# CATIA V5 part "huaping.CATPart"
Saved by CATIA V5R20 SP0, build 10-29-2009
Part number: 花瓶
Material "DS star": density 1000 kg/m3
Material "Bathroom Floor": density 2770 kg/m3, Young's modulus 6e+10 Pa, Poisson ratio 0.3
Bounding box of the stored display mesh (mm): x -48.272 to 51.35, y -48.272 to 48.223, z -0.434 to 150.36
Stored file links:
  F:\huaping.CATPart
  D:\CATIA\win_b64\startup\materials\Catalog.CATMaterial
  D:\CATIA\win_b64\startup\materials\DS_star.jpg
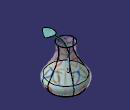
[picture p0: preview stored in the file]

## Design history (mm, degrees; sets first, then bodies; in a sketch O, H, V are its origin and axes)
Body1 (main body), material "DS star"
  Set1
    Plane1: type Offset, RefPlane xy-plane, Offset 20
    Plane2: type Offset, RefPlane Plane1, Offset 20
    Plane3: type Offset, RefPlane Plane2, Offset 20
    Plane4: type Offset, RefPlane Plane3, Offset 20
    Plane5: type Offset, RefPlane Plane4, Offset 20
    Sketch1 on xy-plane, origin (0, 0, 0), H (1, 0, 0), V (0, 1, 0)
      circle A1 centre (0, 0) radius 38.3817
    Sketch2 on Plane2, origin (0, 0, 40), H (1, 0, 0), V (0, 1, 0)
      circle A1 centre (0, 0) radius 37.6815
    Sketch3 on Plane3, origin (0, 0, 60), H (1, 0, 0), V (0, 1, 0)
      circle A1 centre (0, 0) radius 25.6953
    Sketch4 on Plane4, origin (0, 0, 80), H (1, 0, 0), V (0, 1, 0)
      circle A1 centre (0, 0) radius 19.4702
    Sketch5 on Plane5, origin (0, 0, 100), H (1, 0, 0), V (0, 1, 0)
      circle A1 centre (0, 0) radius 20.5162
    Sketch6 on Plane1, origin (0, 0, 20), H (1, 0, 0), V (0, 1, 0)
      circle A1 centre (0, 0) radius 48.3055
  Loft1: solid, Sections (Sketch5; Sketch4; Sketch3; Sketch2; Sketch6; Sketch1)
  Shell1: IntOffset 1, ExtOffset 0
  Shell2: IntOffset 1, Face face of Loft1, ExtOffset 0
Body2, material "Bathroom Floor"
  Sketch7 on zx-plane, origin (0, 0, 0), H (-1, 0, 0), V (0, 0, 1)
    axis line L1 (0, 114.6746) -> (0, -23.121)
    point P3 (0, 27.1114)
    line L2 (0, 27.1114) -> (42.6927, 27.1114)
    arc A1 centre (29.5056, 18.1139) radius 15.9642 from (42.6927, 27.1114) to (31.8602, 2.3244) cw
    line L3 (31.8602, 2.3244) -> (0, 2.3244)
    point P7 (0, 2.3244)
    coincidence: P3 L1, P7 L1
    horizontal: L2 H, L3 H
  Shaft1: profile Sketch7, axis Sketch7.L1, angle 360
  Sketch8 on zx-plane, origin (0, 0, 0), H (-1, 0, 0), V (0, 0, 1)
    point P1 (0, 0)
    arc A1 centre (-101.3663, 45.6205) radius 111.1592 from (0, 0) to (-44.6052, 141.1952) ccw
    point P3 (-44.6052, 141.1952)
    coincidence: P1 V, P1 H
  Plane6: type Normal, Curve Sketch8, RefPoint Sketch8.P3
  Sketch9 on Plane6, origin (94.965, 0, 56.399), H (0, 1, 0), V (-0.5106, 0, 0.8598)
    circle A1 centre (0, 97.1887) radius 2.4921
    point P1 (0, 97.1887)
    point P2 (0, 94.6966)
    coincidence: P1 V, A1 P2, P2 V
  Rib1: profile Sketch9, centre curve Sketch8
  Sketch10 on Plane6, origin (94.965, 0, 56.399), H (0, 1, 0), V (-0.5106, 0, 0.8598)
    spline S1 through (-3.5747, 87.0989) (-15.8891, 102.145) (13.0496, 107.6721) (-3.5747, 87.0989)
    point P1 (-3.5747, 87.0989)
    point P2 (-3.5747, 87.0989)
    coincidence: P1 P2
  Pad1: profile Sketch10, direction (0.8598, 0, 0.5106), length 1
